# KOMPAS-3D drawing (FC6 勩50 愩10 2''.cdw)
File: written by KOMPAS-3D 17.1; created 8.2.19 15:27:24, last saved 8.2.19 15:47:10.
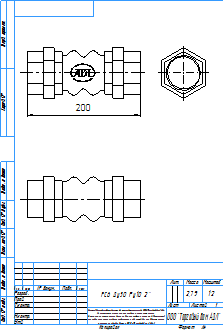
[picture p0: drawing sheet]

Sheet 1: A4, portrait

Title block, sheet 1: name: FC6 Ду50 Ру10 2''; mass: 2,79; sheets: 1; sheet format: A4; stored path: \\adlc.lan\data\АДЛ_ПКД\3D-модели\ADL production\Гибкие вставки серии FC\FC6\KOMPAS 2D\FC6 Ду50 Ру10 2''.cdw

Views: Вид 1
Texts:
  kka
  adl
  Рама для чертежей
  Лит-Масса-Масштаб
  Материал-Предприятие
  Масштаб
  Изм.
  Лист
  № докум.
  Подп.
  Дата
  Лит.
  Разраб.
  Пров.
  Т.контр.
  Листов
  Внимание! Данный продукт является объектом авторского права ООО «Торговый Дом АДЛ».
  Запрещается изменение, копирование, распространение
  (в том числе путем копирования на другие сайты и ресурсы в Интернете)
  или любое иное использование информации и объектов без предварительного
  согласия правообладателя (ООО «Торговый Дом АДЛ»).
  Н.контр.
  Утв.
  ООО "Торговый дом АДЛ"
  Изменение
  Номер документа
  Подпись
  Обозначение документа
  Наименование изделия
  Масса изделия по ГОСТ 2.109-73
  Порядковый номер листа
  Общее количество листов в документе
  Характер работы, выполненной лицом, подписавшим документ
  Наименование или индекс предприятия, выпускающего документ
  Инв. № подл.
  Подп. и дата
  Взам. инв. №
  Инв. № дубл.
  Инвентарный номер подлинника по ГОСТ 2.501-68
  Подпись принявшего подлинник в отдел технической документации
  Инвентарный номер подлинника, взамен которого выпущен данный подлинник
  Инвентарный номер дубликата по ГОСТ 2.502-68
  Подпись принявшего дубликат в отдел технической документации
  Справ. №
  Перв. примен.
  Обозначение документа, взамен или на основании которого выпущен данный документ
  Обозначение документа, в котором впервые записан данный документ
  Подпись лица, копировавшего чертеж
  Обозначение формата листа
  !Рама для чертежа
Dimensions and other numbers on the sheet: 200; 1:2; 1; 2,79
